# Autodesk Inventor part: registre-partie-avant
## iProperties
Author: chr
Created: 2001-06
Part Number: registre-partie-avant
Material: Par défaut
Document SubType Name: Tôlerie
Designer: chr
Control State: 0
Master: False
Checked Out: False
PropertySet Name: Design Tracking Control
Shininess: 21.0
PropertySet Name: _Private Model Information
Length Units: 11269
Angle Units: 11286
Time Units: 11279
Mass Units: 11290
Length Display Precision: 3
Angle Display Precision: 2
Compacted: False
Density: 0.0
Volumn: 0.0
Area: 0.0
PropertySet Name: Model Information
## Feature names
1. Perçage1 [Hole]
2. Perçage2 [Hole]
3. Réseau rectangulaire1 [Rectangular Pattern]
4. Plaque1
5. Plaque2
6. Pli1
7. Plaque3
8. Pli2
9. Plaque4
10. Pli3
11. Plaque5
12. Pli4
